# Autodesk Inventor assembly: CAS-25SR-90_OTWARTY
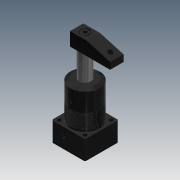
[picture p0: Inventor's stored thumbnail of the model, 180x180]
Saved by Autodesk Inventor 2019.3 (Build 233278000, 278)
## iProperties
Created: 2010-02
Part Number: CAS-25SR-90_OTWARTY
Material: Ogólny
Document SubType Name: Assembly
Designer: CADENGINEERING4
Sending System: PRO/ENGINEER BY PARAMETRIC TECHNOLOGY CORPORATION, 2007170
Preprocessor: PRO/ENGINEER BY PARAMETRIC TECHNOLOGY CORPORATION, 2007170
Title: CAS-25S_ASM
Author: Administrator
Revision Number: 2LAST_VERSION
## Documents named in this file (8)
- D:\Vault_2016\Projekty\STRONA\Pneumatic\Line ; Pipe connecct - type\cas-25s_asm\CAS-25SR-90_OTWARTY.iam
- D:\Vault_2016\Projekty\STRONA\Pneumatic\Line ; Pipe connecct - type\cas-25s_asm\CAS-25BT.ipt
- D:\Vault_2016\Projekty\STRONA\Pneumatic\Line ; Pipe connecct - type\cas-25s_asm\CAS-25SHSG.ipt
- D:\Vault_2016\Projekty\STRONA\Pneumatic\Line ; Pipe connecct - type\cas-25s_asm\CAS-25HG.ipt
- D:\Vault_2016\Projekty\STRONA\Pneumatic\Line ; Pipe connecct - type\cas-25s_asm\PRT0001M3.ipt
- D:\Vault_2016\Projekty\STRONA\Pneumatic\Line ; Pipe connecct - type\cas-25s_asm\CAS-25SYABI.ipt
- D:\Vault_2016\Projekty\STRONA\Pneumatic\Line ; Pipe connecct - type\cas-25s_asm\M6LC.ipt
- D:\Vault_2016\Projekty\STRONA\Pneumatic\Line ; Pipe connecct - type\cas-25s_asm\PRT0001.ipt
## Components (10 placed, 10 different names)
1. CAS-25BT_10 — Kątowe:1
2. CAS-25SHSG_11 — Zestawiające:1, Zestawiające:2
3. CAS-25HG_12
4. PRT0001M3_13
5. PRT0001M3_14
6. PRT0001M3_15
7. PRT0001M3_16
8. CAS-25SYABI_17 — Zestawiające:1, Zestawiające:2, Kątowe:1
9. M6LC_18
10. PRT0001_19
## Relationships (3: Mate 2, Angle 1)
- Zestawiające:1 [Mate]: CAS-25SHSG_11 ↔ CAS-25SYABI_17
- Zestawiające:2 [Mate]: CAS-25SHSG_11 ↔ CAS-25SYABI_17
- Kątowe:1 [Angle]: CAS-25BT_10 ↔ CAS-25SYABI_17
